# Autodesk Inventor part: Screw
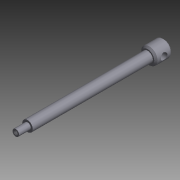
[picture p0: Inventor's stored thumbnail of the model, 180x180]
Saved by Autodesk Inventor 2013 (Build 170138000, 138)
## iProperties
Shininess: 12.0
Length Units: 11272
Angle Units: 11279
Time Units: 11290
Mass Units: 11283
Length Display Precision: 2
Angle Display Precision: 1
Compacted: True
Created: 1999-05
Part Number: Screw
Document SubType Name: Modeling
Designer: Administrator
Density: 7.86 g/cm^3
Material: Steel, Mild
Mass: 93.6133 g
Surface Area: 51.8791 cm^2
Volume: 11.9101 cm^3
Density: 8.94
Volumn: 11.91003151861203
Area: 51.879342766234146
PropertySet Name: Model Information
Control State: 0
Master: False
Checked Out: False
Author: Administrator
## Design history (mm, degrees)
node "y-z Plane"
  node "x-z Plane"
  node "x-y Plane"
node "Extrusion1" dims "d1" = 15.748, "d2" = 0
  sketch "Sketch1"
    geometry: C1 r 7.874 at (0, 0); 1 further point
    constraints: 1 centre point, 1 coincident
    dimensions: "d0" = 15.748 diameter of C1
node "Extrusion2" dims "d3" = 114.3, "d4" = 0
  sketch "Sketch2"
    geometry: C1 r 7.874 at (0, 0) reference; C2 r 5.044 at (0, 0)
    constraints: 1 centre point
node "Extrusion3" dims "d6" = 11.176, "d7" = 0
  sketch "Sketch3"
    geometry: C1 r 5.044 at (0, 0) reference; C2 r 3.175 at (0, 0)
    constraints: 1 centre point
    dimensions: "d5" = 6.35 diameter of C2
node "Hole1" dims "d8" = 3.9624, "d9" = 9.525, "d10" = 6.35, "d11" = 60 deg, "d12" = 3.175, "d13" = 118 deg, "d29" = 19.05
  sketch "Sketch4"
    geometry: C1 r 3.175 at (0, 0) reference
workplane "Work Plane1"
  workaxis "Work Axis1"
workplane "Work Plane2"
workplane "Work Plane3"
node "Hole2" dims "d20" = 6.35, "d21" = 9.525, "d22" = 6.35, "d23" = 60 deg, "d24" = 19.05, "d25" = 118 deg
  sketch "Sketch5"
    geometry: L1 (0, 3.15)-(0, -18.898) reference; L2 (-11.024, 0)-(11.024, 0) reference; 1 further point
    constraints: 1 midpoint
    dimensions: "d28" = 7.874 distance from line of point (0, -7.874) L2
node "Chamfer1" dims "d26" = 1.5875, "d27" = 1.5875, "d30" = 45 deg
workaxis "Work Axis2"
workaxis "Work Axis3"
body "Solid1"
other parameters: "d14" = 45 deg, "d16" = 0, "d17" = 7.874
